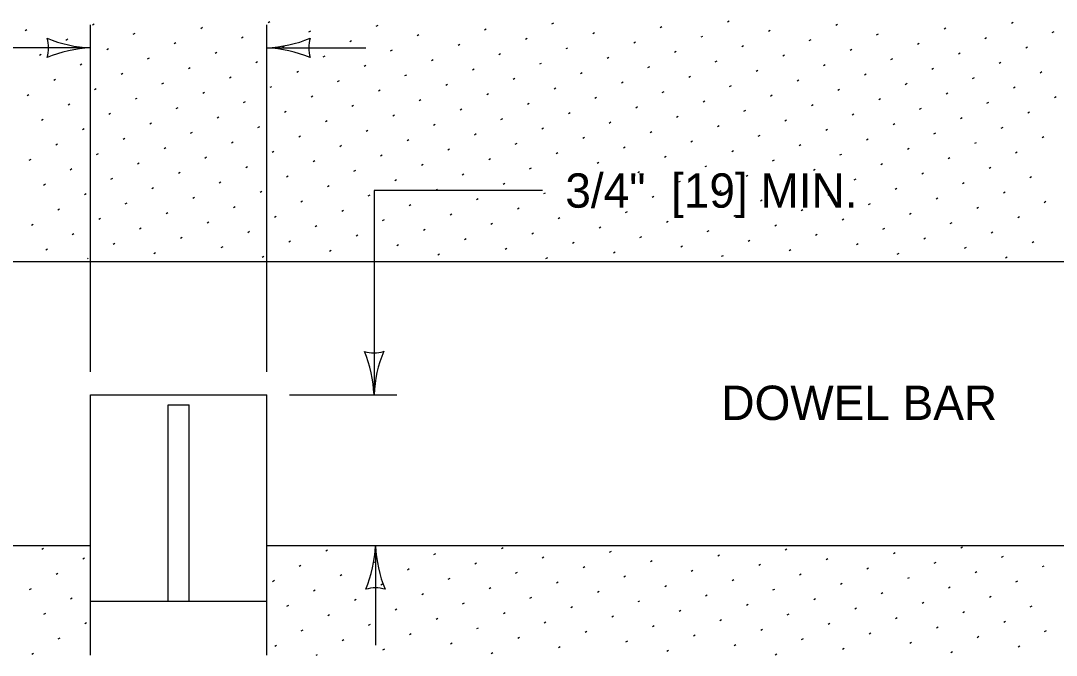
# Model space of a CAD drawing. Extents: x 49991.4 to 50021, y 49987.6 to 50011.4.
# Drawn here: x 50005.88 to 50007.688, y 49993.286 to 49994.395 of the extents above; entities that cross this region are included whole.
import ezdxf

# ---------------------------------------------------------------- set-up
doc = ezdxf.new("R2010")
doc.units = 0
for name, color, linetype in [('Level 1', 7, 'Continuous'), ('Level 2', 7, 'Continuous'), ('Level 3', 7, 'Continuous')]:
    doc.layers.add(name, color=color, linetype=linetype)

msp = doc.modelspace()

# ---------------------------------------------------------------- linework, layer by layer
at = {"layer": 'Level 1'}
for p, q in [((50005.4479, 49993.9739), (50008.0084, 49993.9739)), ((50006.0016, 49993.2857), (50006.0016, 49993.741)), ((50006.0016, 49993.741), (50006.3091, 49993.741)), ((50006.3091, 49993.2857), (50006.3091, 49993.741)), ((50006.137, 49993.7233), (50006.1737, 49993.7233)), ((50006.137, 49993.3804), (50006.137, 49993.7233)), ((50006.1737, 49993.3804), (50006.1737, 49993.7233)), ((50006.0016, 49993.4772), (50005.4479, 49993.4772)), ((50008.0084, 49993.4772), (50006.3091, 49993.4772)), ((50006.0016, 49993.3804), (50006.3091, 49993.3804))]:
    msp.add_line(p, q, dxfattribs=at)
at = {"layer": 'Level 3'}
for p, q in [((50006.0016, 49993.781), (50006.0016, 49994.3876)), ((50006.0049, 49994.3881), (50006.0079, 49994.3898)), ((50006.3091, 49993.781), (50006.3091, 49994.3876)), ((50006.3116, 49994.3919), (50006.3146, 49994.3937)), ((50006.5006, 49994.3856), (50006.5036, 49994.3873)), ((50006.8073, 49994.3895), (50006.8103, 49994.3912)), ((50007.114, 49994.3933), (50007.117, 49994.3951)), ((50007.303, 49994.387), (50007.306, 49994.3887)), ((50007.6097, 49994.3908), (50007.6127, 49994.3926)), ((50005.8872, 49994.3779), (50005.8902, 49994.3796)), ((50006.0762, 49994.3715), (50006.0793, 49994.3733)), ((50006.1939, 49994.3817), (50006.1969, 49994.3835)), ((50006.3829, 49994.3754), (50006.386, 49994.3771)), ((50006.5719, 49994.369), (50006.575, 49994.3708)), ((50006.6896, 49994.3792), (50006.6926, 49994.381)), ((50006.8786, 49994.3729), (50006.8817, 49994.3747)), ((50006.9963, 49994.3831), (50006.9993, 49994.3849)), ((50007.0676, 49994.3666), (50007.0707, 49994.3683)), ((50007.1853, 49994.3768), (50007.1884, 49994.3785)), ((50007.3743, 49994.3704), (50007.3774, 49994.3722)), ((50007.492, 49994.3806), (50007.495, 49994.3824)), ((50007.681, 49994.3743), (50007.6841, 49994.376)), ((50005.9586, 49994.3613), (50005.9616, 49994.3631)), ((50006.1476, 49994.355), (50006.1506, 49994.3567)), ((50006.2652, 49994.3652), (50006.2683, 49994.3669)), ((50006.3366, 49994.3486), (50006.3396, 49994.3504)), ((50006.4543, 49994.3588), (50006.4573, 49994.3606)), ((50006.6433, 49994.3525), (50006.6463, 49994.3542)), ((50006.761, 49994.3627), (50006.764, 49994.3644)), ((50006.95, 49994.3564), (50006.953, 49994.3581)), ((50007.139, 49994.35), (50007.142, 49994.3518)), ((50007.2567, 49994.3602), (50007.2597, 49994.362)), ((50007.4457, 49994.3539), (50007.4487, 49994.3556)), ((50007.5634, 49994.3641), (50007.5664, 49994.3658)), ((50007.6347, 49994.3475), (50007.6377, 49994.3493)), ((50006.0016, 49994.3476), (50005.833, 49994.3476)), ((50005.9122, 49994.3346), (50005.9152, 49994.3363)), ((50006.0299, 49994.3448), (50006.0329, 49994.3465)), ((50006.2189, 49994.3384), (50006.2219, 49994.3402)), ((50006.3091, 49994.3476), (50006.4825, 49994.3476)), ((50006.4079, 49994.3321), (50006.411, 49994.3338)), ((50006.5256, 49994.3423), (50006.5286, 49994.344)), ((50006.7146, 49994.3359), (50006.7176, 49994.3377)), ((50006.8323, 49994.3462), (50006.8353, 49994.3479)), ((50006.9036, 49994.3296), (50006.9067, 49994.3314)), ((50007.0213, 49994.3398), (50007.0243, 49994.3416)), ((50007.2103, 49994.3335), (50007.2134, 49994.3352)), ((50007.328, 49994.3437), (50007.331, 49994.3454)), ((50007.517, 49994.3373), (50007.52, 49994.3391)), ((50005.9836, 49994.318), (50005.9866, 49994.3198)), ((50006.1012, 49994.3282), (50006.1043, 49994.33)), ((50006.1726, 49994.3117), (50006.1756, 49994.3134)), ((50006.2902, 49994.3219), (50006.2933, 49994.3236)), ((50006.4793, 49994.3155), (50006.4823, 49994.3173)), ((50006.5969, 49994.3257), (50006.6, 49994.3275)), ((50006.786, 49994.3194), (50006.789, 49994.3211)), ((50006.975, 49994.3131), (50006.978, 49994.3148)), ((50007.0926, 49994.3233), (50007.0957, 49994.325)), ((50007.2817, 49994.3169), (50007.2847, 49994.3187)), ((50007.3993, 49994.3271), (50007.4024, 49994.3289)), ((50007.5884, 49994.3208), (50007.5914, 49994.3225)), ((50006.0549, 49994.3015), (50006.0579, 49994.3032)), ((50006.2439, 49994.2951), (50006.2469, 49994.2969)), ((50006.3616, 49994.3053), (50006.3646, 49994.3071)), ((50006.5506, 49994.299), (50006.5536, 49994.3007)), ((50006.6683, 49994.3092), (50006.6713, 49994.3109)), ((50006.8573, 49994.3029), (50006.8603, 49994.3046)), ((50007.0463, 49994.2965), (50007.0493, 49994.2983)), ((50007.164, 49994.3067), (50007.167, 49994.3085)), ((50007.353, 49994.3004), (50007.356, 49994.3021)), ((50007.4707, 49994.3106), (50007.4737, 49994.3123)), ((50007.542, 49994.294), (50007.545, 49994.2958)), ((50007.6597, 49994.3042), (50007.6627, 49994.306)), ((50005.9372, 49994.2913), (50005.9402, 49994.293)), ((50006.1262, 49994.2849), (50006.1293, 49994.2867)), ((50006.3152, 49994.2786), (50006.3183, 49994.2803)), ((50006.4329, 49994.2888), (50006.436, 49994.2905)), ((50006.6219, 49994.2824), (50006.625, 49994.2842)), ((50006.7396, 49994.2926), (50006.7426, 49994.2944)), ((50006.811, 49994.2761), (50006.814, 49994.2778)), ((50006.9286, 49994.2863), (50006.9317, 49994.2881)), ((50007.1176, 49994.28), (50007.1207, 49994.2817)), ((50007.2353, 49994.2902), (50007.2384, 49994.2919)), ((50007.4243, 49994.2838), (50007.4274, 49994.2856)), ((50007.6134, 49994.2775), (50007.6164, 49994.2792)), ((50005.8909, 49994.2645), (50005.8939, 49994.2663)), ((50006.0086, 49994.2747), (50006.0116, 49994.2765)), ((50006.0799, 49994.2582), (50006.0829, 49994.2599)), ((50006.1976, 49994.2684), (50006.2006, 49994.2701)), ((50006.3866, 49994.262), (50006.3896, 49994.2638)), ((50006.5043, 49994.2722), (50006.5073, 49994.274)), ((50006.6933, 49994.2659), (50006.6963, 49994.2676)), ((50006.8823, 49994.2595), (50006.8853, 49994.2613)), ((50007, 49994.2698), (50007.003, 49994.2715)), ((50007.189, 49994.2634), (50007.192, 49994.2652)), ((50007.3067, 49994.2736), (50007.3097, 49994.2754)), ((50007.378, 49994.2571), (50007.381, 49994.2588)), ((50007.4957, 49994.2673), (50007.4987, 49994.269)), ((50007.6847, 49994.2609), (50007.6877, 49994.2627)), ((50005.9622, 49994.248), (50005.9652, 49994.2497)), ((50006.1512, 49994.2416), (50006.1543, 49994.2434)), ((50006.2689, 49994.2518), (50006.2719, 49994.2536)), ((50006.4579, 49994.2455), (50006.461, 49994.2472)), ((50006.5756, 49994.2557), (50006.5786, 49994.2574)), ((50006.6469, 49994.2391), (50006.65, 49994.2409)), ((50006.7646, 49994.2493), (50006.7676, 49994.2511)), ((50006.9536, 49994.243), (50006.9567, 49994.2448)), ((50007.0713, 49994.2532), (50007.0743, 49994.255)), ((50007.2603, 49994.2469), (50007.2634, 49994.2486)), ((50007.4493, 49994.2405), (50007.4524, 49994.2423)), ((50007.567, 49994.2507), (50007.57, 49994.2525)), ((50005.9159, 49994.2212), (50005.9189, 49994.223)), ((50006.0336, 49994.2314), (50006.0366, 49994.2332)), ((50006.2226, 49994.2251), (50006.2256, 49994.2268)), ((50006.3402, 49994.2353), (50006.3433, 49994.237)), ((50006.5293, 49994.2289), (50006.5323, 49994.2307)), ((50006.7183, 49994.2226), (50006.7213, 49994.2243)), ((50006.836, 49994.2328), (50006.839, 49994.2345)), ((50007.025, 49994.2265), (50007.028, 49994.2282)), ((50007.1426, 49994.2367), (50007.1457, 49994.2384)), ((50007.3317, 49994.2303), (50007.3347, 49994.2321)), ((50007.5207, 49994.224), (50007.5237, 49994.2257)), ((50007.6384, 49994.2342), (50007.6414, 49994.2359)), ((50005.9872, 49994.2047), (50005.9902, 49994.2064)), ((50006.1049, 49994.2149), (50006.1079, 49994.2166)), ((50006.2939, 49994.2085), (50006.2969, 49994.2103)), ((50006.4116, 49994.2187), (50006.4146, 49994.2205)), ((50006.6006, 49994.2124), (50006.6036, 49994.2141)), ((50006.7896, 49994.206), (50006.7926, 49994.2078)), ((50006.9073, 49994.2162), (50006.9103, 49994.218)), ((50007.0963, 49994.2099), (50007.0993, 49994.2117)), ((50007.214, 49994.2201), (50007.217, 49994.2219)), ((50007.2853, 49994.2036), (50007.2884, 49994.2053)), ((50007.403, 49994.2138), (50007.406, 49994.2155)), ((50007.592, 49994.2074), (50007.595, 49994.2092)), ((50006.0586, 49994.1881), (50006.0616, 49994.1899)), ((50006.1762, 49994.1983), (50006.1793, 49994.2001)), ((50006.3652, 49994.192), (50006.3683, 49994.1937)), ((50006.4829, 49994.2022), (50006.486, 49994.2039)), ((50006.5543, 49994.1856), (50006.5573, 49994.1874)), ((50006.6719, 49994.1958), (50006.675, 49994.1976)), ((50006.861, 49994.1895), (50006.864, 49994.1912)), ((50006.9786, 49994.1997), (50006.9817, 49994.2015)), ((50007.1676, 49994.1934), (50007.1707, 49994.1951)), ((50007.3567, 49994.187), (50007.3597, 49994.1888)), ((50007.4743, 49994.1972), (50007.4774, 49994.199)), ((50007.6634, 49994.1909), (50007.6664, 49994.1926)), ((50005.9409, 49994.1779), (50005.9439, 49994.1797)), ((50006.1299, 49994.1716), (50006.1329, 49994.1733)), ((50006.2476, 49994.1818), (50006.2506, 49994.1835)), ((50006.4366, 49994.1754), (50006.4396, 49994.1772)), ((50006.6256, 49994.1691), (50006.6286, 49994.1708)), ((50006.7433, 49994.1793), (50006.7463, 49994.181)), ((50006.9323, 49994.1729), (50006.9353, 49994.1747)), ((50007.05, 49994.1832), (50007.053, 49994.1849)), ((50007.1213, 49994.1666), (50007.1243, 49994.1684)), ((50007.239, 49994.1768), (50007.242, 49994.1786)), ((50007.428, 49994.1705), (50007.431, 49994.1722)), ((50007.5457, 49994.1807), (50007.5487, 49994.1824)), ((50005.8945, 49994.1511), (50005.8976, 49994.1529)), ((50006.0122, 49994.1614), (50006.0152, 49994.1631)), ((50006.2012, 49994.155), (50006.2043, 49994.1568)), ((50006.3189, 49994.1652), (50006.3219, 49994.167)), ((50006.3902, 49994.1487), (50006.3933, 49994.1504)), ((50006.5079, 49994.1589), (50006.511, 49994.1606)), ((50006.6969, 49994.1525), (50006.7, 49994.1543)), ((50006.8146, 49994.1627), (50006.8176, 49994.1645)), ((50007.0036, 49994.1564), (50007.0067, 49994.1581)), ((50007.1926, 49994.1501), (50007.1957, 49994.1518)), ((50007.3103, 49994.1603), (50007.3134, 49994.162)), ((50007.4993, 49994.1539), (50007.5024, 49994.1557)), ((50007.617, 49994.1641), (50007.62, 49994.1659)), ((50005.9659, 49994.1346), (50005.9689, 49994.1364)), ((50006.0836, 49994.1448), (50006.0866, 49994.1466)), ((50006.2726, 49994.1385), (50006.2756, 49994.1402)), ((50006.4616, 49994.1321), (50006.4646, 49994.1339)), ((50006.5793, 49994.1423), (50006.5823, 49994.1441)), ((50006.7683, 49994.136), (50006.7713, 49994.1377)), ((50006.886, 49994.1462), (50006.889, 49994.1479)), ((50007.075, 49994.1399), (50007.078, 49994.1416)), ((50007.264, 49994.1335), (50007.267, 49994.1353)), ((50007.3817, 49994.1437), (50007.3847, 49994.1455)), ((50007.5707, 49994.1374), (50007.5737, 49994.1391)), ((50006.0372, 49994.1181), (50006.0402, 49994.1198)), ((50006.1549, 49994.1283), (50006.1579, 49994.13)), ((50006.3439, 49994.1219), (50006.3469, 49994.1237)), ((50006.5329, 49994.1156), (50006.536, 49994.1173)), ((50006.6506, 49994.1258), (50006.6536, 49994.1275)), ((50006.8396, 49994.1194), (50006.8426, 49994.1212)), ((50006.9573, 49994.1296), (50006.9603, 49994.1314)), ((50007.0286, 49994.1131), (50007.0317, 49994.1148)), ((50007.1463, 49994.1233), (50007.1493, 49994.1251)), ((50007.3353, 49994.117), (50007.3384, 49994.1187)), ((50007.453, 49994.1272), (50007.456, 49994.1289)), ((50007.642, 49994.1208), (50007.645, 49994.1226)), ((50005.9195, 49994.1078), (50005.9226, 49994.1096)), ((50006.1086, 49994.1015), (50006.1116, 49994.1033)), ((50006.2262, 49994.1117), (50006.2293, 49994.1135)), ((50006.2976, 49994.0952), (50006.3006, 49994.0969)), ((50006.4152, 49994.1054), (50006.4183, 49994.1071)), ((50006.4966, 49994.0982), (50006.4966, 49993.7418)), ((50006.7907, 49994.0982), (50006.4966, 49994.0982)), ((50006.6043, 49994.099), (50006.6073, 49994.1008)), ((50006.7219, 49994.1092), (50006.725, 49994.111)), ((50006.911, 49994.1029), (50006.914, 49994.1046)), ((50007.1, 49994.0965), (50007.103, 49994.0983)), ((50007.2176, 49994.1068), (50007.2207, 49994.1085)), ((50007.4067, 49994.1004), (50007.4097, 49994.1022)), ((50007.5243, 49994.1106), (50007.5274, 49994.1124)), ((50007.5957, 49994.0941), (50007.5987, 49994.0958)), ((50005.9909, 49994.0913), (50005.9939, 49994.0931)), ((50006.1799, 49994.085), (50006.1829, 49994.0867)), ((50006.3689, 49994.0786), (50006.3719, 49994.0804)), ((50006.4866, 49994.0888), (50006.4896, 49994.0906)), ((50006.6756, 49994.0825), (50006.6786, 49994.0842)), ((50006.7933, 49994.0927), (50006.7963, 49994.0944)), ((50006.8646, 49994.0761), (50006.8676, 49994.0779)), ((50006.9823, 49994.0863), (50006.9853, 49994.0881)), ((50007.1713, 49994.08), (50007.1743, 49994.0818)), ((50007.289, 49994.0902), (50007.292, 49994.092)), ((50007.478, 49994.0839), (50007.481, 49994.0856)), ((50007.667, 49994.0775), (50007.67, 49994.0793)), ((50005.9445, 49994.0645), (50005.9476, 49994.0663)), ((50006.0622, 49994.0748), (50006.0652, 49994.0765)), ((50006.1336, 49994.0582), (50006.1366, 49994.06)), ((50006.2512, 49994.0684), (50006.2543, 49994.0702)), ((50006.4402, 49994.0621), (50006.4433, 49994.0638)), ((50006.5579, 49994.0723), (50006.561, 49994.074)), ((50006.7469, 49994.0659), (50006.75, 49994.0677)), ((50006.936, 49994.0596), (50006.939, 49994.0613)), ((50007.0536, 49994.0698), (50007.0567, 49994.0715)), ((50007.2426, 49994.0635), (50007.2457, 49994.0652)), ((50007.3603, 49994.0737), (50007.3634, 49994.0754)), ((50007.5493, 49994.0673), (50007.5524, 49994.0691)), ((50006.0159, 49994.048), (50006.0189, 49994.0497)), ((50006.2049, 49994.0417), (50006.2079, 49994.0434)), ((50006.3226, 49994.0519), (50006.3256, 49994.0536)), ((50006.5116, 49994.0455), (50006.5146, 49994.0473)), ((50006.6293, 49994.0557), (50006.6323, 49994.0575)), ((50006.8183, 49994.0494), (50006.8213, 49994.0511)), ((50007.0073, 49994.043), (50007.0103, 49994.0448)), ((50007.125, 49994.0532), (50007.128, 49994.055)), ((50007.314, 49994.0469), (50007.317, 49994.0487)), ((50007.4317, 49994.0571), (50007.4347, 49994.0589)), ((50007.503, 49994.0406), (50007.506, 49994.0423)), ((50007.6207, 49994.0508), (50007.6237, 49994.0525)), ((50005.8982, 49994.0378), (50005.9012, 49994.0395)), ((50006.0872, 49994.0315), (50006.0902, 49994.0332)), ((50006.2762, 49994.0251), (50006.2793, 49994.0269)), ((50006.3939, 49994.0353), (50006.3969, 49994.0371)), ((50006.5829, 49994.029), (50006.586, 49994.0307)), ((50006.7006, 49994.0392), (50006.7036, 49994.0409)), ((50006.7719, 49994.0226), (50006.775, 49994.0244)), ((50006.8896, 49994.0328), (50006.8926, 49994.0346)), ((50007.0786, 49994.0265), (50007.0817, 49994.0282)), ((50007.1963, 49994.0367), (50007.1993, 49994.0385)), ((50007.3853, 49994.0304), (50007.3884, 49994.0321)), ((50007.5743, 49994.024), (50007.5774, 49994.0258)), ((50005.9695, 49994.0212), (50005.9726, 49994.023)), ((50006.0409, 49994.0047), (50006.0439, 49994.0064)), ((50006.1586, 49994.0149), (50006.1616, 49994.0167)), ((50006.3476, 49994.0086), (50006.3506, 49994.0103)), ((50006.4652, 49994.0188), (50006.4683, 49994.0205)), ((50006.6543, 49994.0124), (50006.6573, 49994.0142)), ((50006.8433, 49994.0061), (50006.8463, 49994.0078)), ((50006.961, 49994.0163), (50006.964, 49994.018)), ((50007.15, 49994.0099), (50007.153, 49994.0117)), ((50007.2676, 49994.0202), (50007.2707, 49994.0219)), ((50007.339, 49994.0036), (50007.342, 49994.0054)), ((50007.4567, 49994.0138), (50007.4597, 49994.0156)), ((50007.6457, 49994.0075), (50007.6487, 49994.0092)), ((50005.9232, 49993.9945), (50005.9262, 49993.9962)), ((50006.1122, 49993.9882), (50006.1152, 49993.9899)), ((50006.2299, 49993.9984), (50006.2329, 49994.0001)), ((50006.4189, 49993.992), (50006.4219, 49993.9938)), ((50006.5366, 49994.0022), (50006.5396, 49994.004)), ((50006.6079, 49993.9857), (50006.611, 49993.9874)), ((50006.7256, 49993.9959), (50006.7286, 49993.9976)), ((50006.9146, 49993.9895), (50006.9176, 49993.9913)), ((50007.0323, 49993.9997), (50007.0353, 49994.0015)), ((50007.2213, 49993.9934), (50007.2243, 49993.9951)), ((50007.4103, 49993.9871), (50007.4134, 49993.9888)), ((50007.528, 49993.9973), (50007.531, 49993.999)), ((50005.9961, 49993.9788), (50005.9976, 49993.9797)), ((50006.3012, 49993.9818), (50006.3043, 49993.9836)), ((50006.7969, 49993.9793), (50006.8, 49993.9811)), ((50007.1036, 49993.9832), (50007.1067, 49993.9849)), ((50007.5993, 49993.9807), (50007.6024, 49993.9825)), ((50006.3491, 49993.741), (50006.5366, 49993.741)), ((50005.9165, 49993.471), (50005.9195, 49993.4728)), ((50006.4122, 49993.4685), (50006.4152, 49993.4703)), ((50006.4991, 49993.4772), (50006.4991, 49993.3037)), ((50006.6012, 49993.4622), (50006.6043, 49993.4639)), ((50006.7189, 49993.4724), (50006.7219, 49993.4741)), ((50006.9079, 49993.4661), (50006.911, 49993.4678)), ((50007.2146, 49993.4699), (50007.2176, 49993.4717)), ((50007.4036, 49993.4636), (50007.4067, 49993.4653)), ((50007.5213, 49993.4738), (50007.5243, 49993.4755)), ((50005.9878, 49993.4545), (50005.9909, 49993.4562)), ((50006.4982, 49993.4476), (50006.5, 49993.4506)), ((50006.6726, 49993.4456), (50006.6756, 49993.4474)), ((50006.7902, 49993.4559), (50006.7933, 49993.4576)), ((50006.9793, 49993.4495), (50006.9823, 49993.4513)), ((50007.0969, 49993.4597), (50007.1, 49993.4615)), ((50007.1683, 49993.4432), (50007.1713, 49993.4449)), ((50007.286, 49993.4534), (50007.289, 49993.4551)), ((50007.475, 49993.447), (50007.478, 49993.4488)), ((50007.5926, 49993.4572), (50007.5957, 49993.459)), ((50005.9415, 49993.4277), (50005.9445, 49993.4295)), ((50006.3659, 49993.4418), (50006.3689, 49993.4435)), ((50006.4372, 49993.4252), (50006.4402, 49993.427)), ((50006.5549, 49993.4354), (50006.5579, 49993.4372)), ((50006.7439, 49993.4291), (50006.7469, 49993.4308)), ((50006.8616, 49993.4393), (50006.8646, 49993.4411)), ((50007.0506, 49993.433), (50007.0536, 49993.4347)), ((50007.2396, 49993.4266), (50007.2426, 49993.4284)), ((50007.3573, 49993.4368), (50007.3603, 49993.4386)), ((50007.5463, 49993.4305), (50007.5493, 49993.4322)), ((50007.664, 49993.4407), (50007.667, 49993.4424)), ((50006.3195, 49993.415), (50006.3226, 49993.4168)), ((50006.5086, 49993.4087), (50006.5116, 49993.4104)), ((50006.6262, 49993.4189), (50006.6293, 49993.4206)), ((50006.8152, 49993.4125), (50006.8183, 49993.4143)), ((50006.9329, 49993.4228), (50006.936, 49993.4245)), ((50007.1219, 49993.4164), (50007.125, 49993.4182)), ((50007.311, 49993.4101), (50007.314, 49993.4118)), ((50007.4286, 49993.4203), (50007.4317, 49993.422)), ((50007.6176, 49993.4139), (50007.6207, 49993.4157)), ((50005.8952, 49993.401), (50005.8982, 49993.4027)), ((50006.3909, 49993.3985), (50006.3939, 49993.4002)), ((50006.5799, 49993.3921), (50006.5829, 49993.3939)), ((50006.6976, 49993.4023), (50006.7006, 49993.4041)), ((50006.8866, 49993.396), (50006.8896, 49993.3978)), ((50007.0043, 49993.4062), (50007.0073, 49993.408)), ((50007.0756, 49993.3897), (50007.0786, 49993.3914)), ((50007.1933, 49993.3999), (50007.1963, 49993.4016)), ((50007.3823, 49993.3935), (50007.3853, 49993.3953)), ((50007.5, 49993.4037), (50007.503, 49993.4055)), ((50005.9665, 49993.3844), (50005.9695, 49993.3862)), ((50006.3445, 49993.3717), (50006.3476, 49993.3735)), ((50006.4622, 49993.3819), (50006.4652, 49993.3837)), ((50006.6512, 49993.3756), (50006.6543, 49993.3773)), ((50006.7689, 49993.3858), (50006.7719, 49993.3875)), ((50006.9579, 49993.3795), (50006.961, 49993.3812)), ((50007.1469, 49993.3731), (50007.15, 49993.3749)), ((50007.2646, 49993.3833), (50007.2676, 49993.3851)), ((50007.4536, 49993.377), (50007.4567, 49993.3787)), ((50007.5713, 49993.3872), (50007.5743, 49993.3889)), ((50007.6426, 49993.3706), (50007.6457, 49993.3724)), ((50005.9202, 49993.3577), (50005.9232, 49993.3594)), ((50006.4159, 49993.3552), (50006.4189, 49993.3569)), ((50006.5336, 49993.3654), (50006.5366, 49993.3671)), ((50006.7226, 49993.359), (50006.7256, 49993.3608)), ((50006.8402, 49993.3692), (50006.8433, 49993.371)), ((50006.9116, 49993.3527), (50006.9146, 49993.3545)), ((50007.0293, 49993.3629), (50007.0323, 49993.3647)), ((50007.2183, 49993.3566), (50007.2213, 49993.3583)), ((50007.336, 49993.3668), (50007.339, 49993.3685)), ((50007.525, 49993.3604), (50007.528, 49993.3622)), ((50005.9915, 49993.3411), (50005.9945, 49993.3429)), ((50006.4872, 49993.3386), (50006.4902, 49993.3404)), ((50006.6049, 49993.3488), (50006.6079, 49993.3506)), ((50006.7939, 49993.3425), (50006.7969, 49993.3442)), ((50006.9829, 49993.3362), (50006.986, 49993.3379)), ((50007.1006, 49993.3464), (50007.1036, 49993.3481)), ((50007.2896, 49993.34), (50007.2926, 49993.3418)), ((50007.4073, 49993.3502), (50007.4103, 49993.352)), ((50007.5963, 49993.3439), (50007.5993, 49993.3456)), ((50006.3695, 49993.3284), (50006.3726, 49993.3302)), ((50006.5586, 49993.3221), (50006.5616, 49993.3238)), ((50006.6762, 49993.3323), (50006.6793, 49993.334)), ((50006.8652, 49993.3259), (50006.8683, 49993.3277)), ((50007.0543, 49993.3196), (50007.0573, 49993.3214)), ((50007.1719, 49993.3298), (50007.175, 49993.3316)), ((50007.361, 49993.3235), (50007.364, 49993.3252)), ((50007.4786, 49993.3337), (50007.4817, 49993.3354)), ((50007.55, 49993.3171), (50007.553, 49993.3189)), ((50007.6676, 49993.3273), (50007.6707, 49993.3291)), ((50005.9452, 49993.3144), (50005.9482, 49993.3161)), ((50006.3232, 49993.3017), (50006.3262, 49993.3034)), ((50006.4409, 49993.3119), (50006.4439, 49993.3136)), ((50006.6299, 49993.3055), (50006.6329, 49993.3073)), ((50006.7476, 49993.3157), (50006.7506, 49993.3175)), ((50006.8189, 49993.2992), (50006.8219, 49993.3009)), ((50006.9366, 49993.3094), (50006.9396, 49993.3111)), ((50007.1256, 49993.3031), (50007.1286, 49993.3048)), ((50007.2433, 49993.3133), (50007.2463, 49993.315)), ((50007.4323, 49993.3069), (50007.4353, 49993.3087)), ((50007.6213, 49993.3006), (50007.6243, 49993.3023)), ((50005.8988, 49993.2876), (50005.9019, 49993.2894)), ((50006.3956, 49993.2857), (50006.3976, 49993.2869)), ((50006.5122, 49993.2953), (50006.5152, 49993.2971)), ((50006.7012, 49993.289), (50006.7043, 49993.2907)), ((50007.0079, 49993.2929), (50007.011, 49993.2946)), ((50007.1969, 49993.2865), (50007.2, 49993.2883)), ((50007.3146, 49993.2967), (50007.3176, 49993.2985)), ((50007.5036, 49993.2904), (50007.5067, 49993.2921))]:
    msp.add_line(p, q, dxfattribs=at)
for centre, radius, start, end in [((50006.0108, 49994.5697), 0.2223, 247.456, 267.6395), ((50005.8734, 49994.3476), 0.0548, 342.1388, 17.8612), ((50006.2976, 49994.5803), 0.233, 272.8273, 292.0772), ((50006.4373, 49994.3476), 0.0548, 162.1388, 197.8612), ((50006.0131, 49994.1149), 0.233, 92.8273, 112.0772), ((50006.2999, 49994.1254), 0.2223, 67.456, 87.6395), ((50006.4966, 49993.8692), 0.0548, 252.1388, 287.8612), ((50006.2639, 49993.7295), 0.233, 2.8273, 22.0772), ((50006.7188, 49993.7319), 0.2223, 157.456, 177.6395), ((50006.2769, 49993.4863), 0.2223, 337.456, 357.6395), ((50006.7318, 49993.4887), 0.233, 182.8273, 202.0772), ((50006.4991, 49993.3489), 0.0548, 72.1388, 107.8612)]:
    msp.add_arc(centre, radius, start, end, dxfattribs=at)

# ---------------------------------------------------------------- texts
at = {"layer": 'Level 2'}
for s, p in [('3/4"  [19] MIN.', (50006.8307, 49994.0682)), ('DOWEL BAR', (50007.1032, 49993.6971))]:
    msp.add_text(s, height=0.06, dxfattribs=at).set_placement(p)

doc.saveas('drawing.dxf')
